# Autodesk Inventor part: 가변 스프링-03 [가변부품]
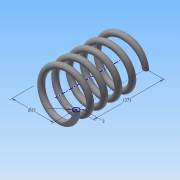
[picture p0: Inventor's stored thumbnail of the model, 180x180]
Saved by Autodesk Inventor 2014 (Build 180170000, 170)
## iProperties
Created: 2015-09
Part Number: 가변 스프링-03 [가변부품]
Material: 강철, 탄소
Document SubType Name: Modeling
Designer: study
Density: 7.87 g/cm^3
Appearance: 반연마
Mass: 18.7632 g
Surface Area: 32.415 cm^2
Volume: 2.38414 cm^3
Author: study
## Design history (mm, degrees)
sketch "스케치1"
  geometry: L1 (0, 0)-(11, 0); L2 (11, 0)-(11, 29.043); L3 (11, 29.043)-(0, 29.043); L4 (0, 29.043)-(0, 0); C1 r 1.5 at (11, 0)
  constraints: 8 end point, 2 parallel, 1 centre point, 1 coincident, 1 horizontal, 1 perpendicular
  dimensions: "d0" = 3 diameter of C1; "d1" = 29.04259 distance between parallel lines of L3 L1 (derived); "d2" = 22 diameter of L2 L4
feature "코일1" sketch "스케치1" pitch "d3" = 10; turns "d5" = 5; dims "d4" = 29.04259 (= d1), "d6" = 0, angle "d7" = 90 deg, angle "d8" = 90 deg, "d9" = 0, "d10" = 0
node "작업 평면1"
sketch "스케치2"
  geometry: L1 (-12.5, 0)-(-9.5, 0) reference; 1 further point
  constraints: 1 horizontal alignment
extrude "돌출1" cut sketch "스케치2" stored distance "d12" = 10; taper "d13" = 0 deg
node "작업 평면2"
sketch "스케치3"
  geometry: L1 (-9.5, 0)-(-12.5, 0) reference; 1 further point
  constraints: 1 horizontal alignment
extrude "돌출2" cut sketch "스케치3" stored distance "d15" = 10; taper "d16" = 0 deg
node "솔리드1"
node "절단 모서리 투영1"
node "절단 모서리 투영2"
other parameters: "d11" = 0, "d14" = 29.04259 (= d1)
